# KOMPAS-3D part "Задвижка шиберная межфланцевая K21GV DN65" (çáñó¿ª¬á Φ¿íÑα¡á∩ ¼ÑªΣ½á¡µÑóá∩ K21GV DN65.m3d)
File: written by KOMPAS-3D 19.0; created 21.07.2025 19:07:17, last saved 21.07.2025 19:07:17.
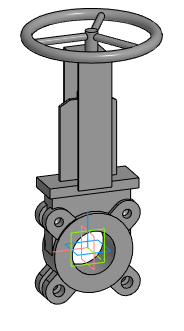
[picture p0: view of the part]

Document properties: Автор: Евгений; Полное имя файла: E:\Dendor Работа Сачек\3D для проектировщиков\2.3 Тип K21GV. Задвижка шиберная межфланцевая\stp_Задвижка шиберная K21GV DN50-400 с маховиком\Задвижка шиберная межфланцевая K21GV DN65.m3d

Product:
- Part/product: Задвижка шиберная межфланцевая K21GV DN65

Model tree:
1. Операция без истории:1  (labels: Задвижка шиберная межфланцевая K21GV DN65)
